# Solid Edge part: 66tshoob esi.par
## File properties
Author: KULL
Template: Iso Metric Part.par
Last saved by: KULL
Revision: 29
Application: Solid Edge
Accuracy: 0,990
Face Style: Model Default
Fill Style: Normal
Coef. of Thermal Exp: 0.0
Thermal Conductivity: 0.0
Specific Heat: 0.0
Modulus of Elasticity: 0.0
Poisson's Ratio: 0.0
Yield Stress: 0.0
Ultimate Stress: 0.0
Elongation: 0.0
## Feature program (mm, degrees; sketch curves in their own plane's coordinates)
base feature "unnamed BaseFeature 1"
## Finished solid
Body 1: sheet body, 1 face, 22 edges, 21 vertices.
  Faces by surface: plane 1
  Edges by curve: circle 15, line 7
Body 2: solid body, 348 faces, 785 edges, 436 vertices.
  Faces by surface: cylinder 146, torus 120, plane 51, blend 22, sphere 8, cone 1
  Edges by curve: circle 472, line 267, intersection 46
Bounding box of the edges (mm; curved faces can reach further): 82.000 x 75.000 x 21.811, from (-41, 32, -6) to (41, 107, 15.811).
Cylindrical faces by radius (mm): R0.2 x4, R0.4 x40, R0.6 x12, R1 x48, R1.5 x1, R2 x12, R2.5 x2, R3 x1, R4 x2, R5 x4, R6 x2, R10 x2, R12 x2, R15 x2, R25 x2, R28 x2, R30 x4, R32 x2, R35 x2
Conical faces (half-angle, radius in mm at the cone's reference point): 31.8829 deg R2.9933 x1
Toroidal faces (ring radius, tube radius in mm): R0.4 r0.6 x2, R1 r0.6 x2, R1 r1 x2, R1.4 r0.4 x16, R1.6 r0.4 x2, R1.6 r0.6 x4, R2.4 r0.4 x18, R2.8 r0.2 x2, R3 r1 x2, R3.0248 r0.6813 x1, R3.2681 r0.3237 x1, R3.8 r0.2 x4, R4.4 r0.6 x4, R4.6 r0.4 x4, R5.0885 r1 x2, R6 r1 x8, R6.3246 r1 x3, R6.4 r0.4 x4, R6.9282 r1 x1, R6.9533 r1 x2, R11 r1 x4, R11.6 r0.4 x2, R13 r1 x2, R14.6 r0.4 x4, R25.4 r0.4 x4, R27 r1 x2, R28.4 r0.4 x2, R29 r1 x4, R31 r1 x4, R31.6 r0.4 x2, R33 r1 x2, R34.6 r0.4 x4
Spherical faces by radius (mm): R1 x6, R4 x1, R6 x1
Planar faces by outward normal: +x 10, -x 10, oblique 31
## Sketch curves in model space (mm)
circle centre (36, 37, 10.811) radius 2.5
line (-3.8397, 95.7022, 0.8949) -> (3.8397, 95.7022, 0.8949)
line (-32.616, 66.5, 5.8278) -> (-3.8397, 102.2674, -0.2141)
arc centre (-9.1133, 48.1158, 8.9333) radius 30 from (-39.1133, 48.1158, 8.9333) through (-37.4424, 57.8501, 7.2889) to (-32.616, 66.5, 5.8278)
line (-39.1133, 48.1158, 8.9333) -> (-39.1133, 37, 10.811)
line (-36, 37, 10.811) -> (-39.1133, 37, 10.811)
line (-36, 46.4352, 9.2172) -> (-36, 37, 10.811)
line (-30, 46.4352, 9.2172) -> (-36, 46.4352, 9.2172)
line (-30, 46.4352, 9.2172) -> (-30, 37, 10.811)
line (-21.6457, 37, 10.811) -> (-30, 37, 10.811)
line (-21.6457, 49.5988, 8.6828) -> (-21.6457, 37, 10.811)
arc centre (8.3543, 49.5988, 8.6828) radius 30 from (-21.6457, 49.5988, 8.6828) through (-20.4009, 58.0313, 7.2583) to (-16.7699, 65.7641, 5.9521)
line (-16.7699, 65.7641, 5.9521) -> (-11.3149, 74.007, 4.5597)
arc centre (-2.9402, 68.6186, 5.4699) radius 10 from (-11.3149, 74.007, 4.5597) through (-7.7021, 77.2892, 4.0053) to (-2.9402, 78.4789, 3.8043)
line (-2.9402, 78.4789, 3.8043) -> (2.9402, 78.4789, 3.8043)
arc centre (2.9402, 68.6186, 5.4699) radius 10 from (11.3149, 74.007, 4.5597) through (7.7021, 77.2892, 4.0053) to (2.9402, 78.4789, 3.8043)
line (16.7699, 65.7641, 5.9521) -> (11.3149, 74.007, 4.5597)
arc centre (-8.3543, 49.5988, 8.6828) radius 30 from (21.6457, 49.5988, 8.6828) through (20.4009, 58.0313, 7.2583) to (16.7699, 65.7641, 5.9521)
line (21.6457, 49.5988, 8.6828) -> (21.6457, 37, 10.811)
line (21.6457, 37, 10.811) -> (30, 37, 10.811)
line (30, 37, 10.811) -> (30, 46.4352, 9.2172)
line (30, 46.4352, 9.2172) -> (36, 46.4352, 9.2172)
line (36, 37, 10.811) -> (36, 46.4352, 9.2172)
line (36, 37, 10.811) -> (39.1133, 37, 10.811)
line (39.1133, 48.1158, 8.9333) -> (39.1133, 37, 10.811)
arc centre (9.1133, 48.1158, 8.9333) radius 30 from (32.616, 66.5, 5.8278) through (37.4424, 57.8501, 7.2889) to (39.1133, 48.1158, 8.9333)
line (32.616, 66.5, 5.8278) -> (3.8397, 102.2674, -0.2141)
arc centre (-3.8071, 84.8559, 2.7271) radius 6 from (-8.5076, 88.5327, 2.106) through (-6.4173, 90.1829, 1.8272) to (-3.8071, 90.772, 1.7277)
line (-3.8071, 90.772, 1.7277) -> (3.8071, 90.772, 1.7277)
arc centre (3.8071, 84.8559, 2.7271) radius 6 from (3.8071, 90.772, 1.7277) through (6.4173, 90.1829, 1.8272) to (8.5076, 88.5327, 2.106)
line (8.5076, 88.5327, 2.106) -> (28.6988, 63.436, 6.3454)
arc centre (9.1133, 48.1158, 8.9333) radius 25 from (28.6988, 63.436, 6.3454) through (31.2832, 59.5085, 7.0088) to (33.0678, 55.17, 7.7417)
arc centre (30.1932, 54.3235, 7.8847) radius 3 from (30.1932, 51.3654, 8.3844) through (32.599, 52.5562, 8.1832) to (33.0678, 55.17, 7.7417)
line (30.1932, 51.3654, 8.3844) -> (28.4509, 51.3654, 8.3844)
arc centre (28.4509, 53.3374, 8.0512) radius 2 from (26.4614, 53.1353, 8.0854) through (27.1553, 51.8351, 8.305) to (28.4509, 51.3654, 8.3844)
arc centre (-8.3543, 49.5988, 8.6828) radius 35 from (26.4614, 53.1353, 8.0854) through (24.6374, 61.121, 6.7364) to (20.9572, 68.4583, 5.497)
line (20.9572, 68.4583, 5.497) -> (15.5023, 76.7013, 4.1046)
arc centre (2.9402, 68.6186, 5.4699) radius 15 from (15.5023, 76.7013, 4.1046) through (10.0831, 81.6244, 3.2729) to (2.9402, 83.4091, 2.9715)
line (2.9402, 83.4091, 2.9715) -> (-2.9402, 83.4091, 2.9715)
arc centre (-2.9402, 68.6186, 5.4699) radius 15 from (-2.9402, 83.4091, 2.9715) through (-10.0831, 81.6244, 3.2729) to (-15.5023, 76.7013, 4.1046)
line (-15.5023, 76.7013, 4.1046) -> (-20.9572, 68.4583, 5.497)
arc centre (8.3543, 49.5988, 8.6828) radius 35 from (-20.9572, 68.4583, 5.497) through (-24.6374, 61.121, 6.7364) to (-26.4614, 53.1353, 8.0854)
arc centre (-28.4509, 53.3374, 8.0512) radius 2 from (-28.4509, 51.3654, 8.3844) through (-27.0681, 51.9127, 8.2919) to (-26.4614, 53.1353, 8.0854)
line (-28.4509, 51.3654, 8.3844) -> (-30.1932, 51.3654, 8.3844)
arc centre (-30.1932, 54.3235, 7.8847) radius 3 from (-33.0678, 55.17, 7.7417) through (-32.599, 52.5562, 8.1832) to (-30.1932, 51.3654, 8.3844)
arc centre (-9.1133, 48.1158, 8.9333) radius 25 from (-33.0678, 55.17, 7.7417) through (-31.2832, 59.5085, 7.0088) to (-28.6988, 63.436, 6.3454)
line (-28.6988, 63.436, 6.3454) -> (-8.5076, 88.5327, 2.106)
line (-29.4823, 64.0488, 6.2419) -> (-7.1891, 91.7581, 1.5612)
line (-7.1891, 91.7581, 1.5612) -> (7.1891, 91.7581, 1.5612)
line (7.1891, 91.7581, 1.5612) -> (29.4823, 64.0488, 6.2419)
arc centre (9.1133, 48.1158, 8.9333) radius 26 from (29.4823, 64.0488, 6.2419) through (33.2631, 57.6137, 7.3289) to (35.0117, 50.3793, 8.5509)
line (35.0117, 50.3793, 8.5509) -> (26, 50.3793, 8.5509)
line (26, 50.3793, 8.5509) -> (26, 40.9441, 10.1447)
line (26, 40.9441, 10.1447) -> (25.6457, 40.9441, 10.1447)
line (25.6457, 40.9441, 10.1447) -> (25.6457, 49.5988, 8.6828)
arc centre (-8.3543, 49.5988, 8.6828) radius 34 from (25.6457, 49.5988, 8.6828) through (24.235, 59.1557, 7.0684) to (20.1198, 67.9195, 5.588)
line (20.1198, 67.9195, 5.588) -> (14.6648, 76.1624, 4.1956)
arc centre (2.9402, 68.6186, 5.4699) radius 14 from (14.6648, 76.1624, 4.1956) through (9.6069, 80.7574, 3.4194) to (2.9402, 82.423, 3.1381)
line (2.9402, 82.423, 3.1381) -> (-2.9402, 82.423, 3.1381)
arc centre (-2.9402, 68.6186, 5.4699) radius 14 from (-2.9402, 82.423, 3.1381) through (-9.6069, 80.7574, 3.4194) to (-14.6648, 76.1624, 4.1956)
line (-14.6648, 76.1624, 4.1956) -> (-20.1198, 67.9195, 5.588)
arc centre (8.3543, 49.5988, 8.6828) radius 34 from (-20.1198, 67.9195, 5.588) through (-24.235, 59.1557, 7.0684) to (-25.6457, 49.5988, 8.6828)
line (-25.6457, 49.5988, 8.6828) -> (-25.6457, 40.9441, 10.1447)
line (-25.6457, 40.9441, 10.1447) -> (-26, 40.9441, 10.1447)
line (-26, 40.9441, 10.1447) -> (-26, 50.3793, 8.5509)
line (-26, 50.3793, 8.5509) -> (-35.0117, 50.3793, 8.5509)
arc centre (-9.1133, 48.1158, 8.9333) radius 26 from (-35.0117, 50.3793, 8.5509) through (-33.2631, 57.6137, 7.3289) to (-29.4823, 64.0488, 6.2419)
circle centre (30, 37, 10.811) radius 5
circle centre (36, 37, 10.811) radius 5
circle centre (0, 101, 0) radius 7
line (0, 37, 10.811) -> (0, 101, 0)
line (0, 37, 56.811) -> (0, 101, 46)
circle centre (0, 75.2096, 9.2611) radius 1.5
arc centre (0, 79.7697, 3.5863) radius 4 from (0, 82.514, 6.4964) through (0, 82.2753, 0.4682) to (0, 76.3371, 1.5327)
line (0, 72.6351, 7.721) -> (0, 76.3371, 1.5327)
arc centre (0, 75.2096, 9.2611) radius 3 from (0, 72.6351, 7.721) through (0, 73.3304, 11.5996) to (0, 77.2678, 11.4437)
line (0, 77.2678, 11.4437) -> (0, 82.514, 6.4964)
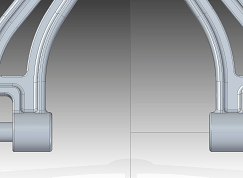
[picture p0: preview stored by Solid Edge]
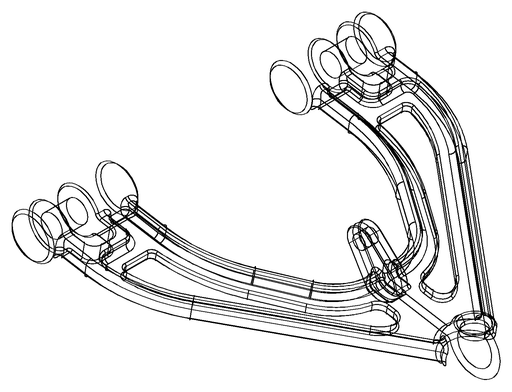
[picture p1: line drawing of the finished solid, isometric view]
